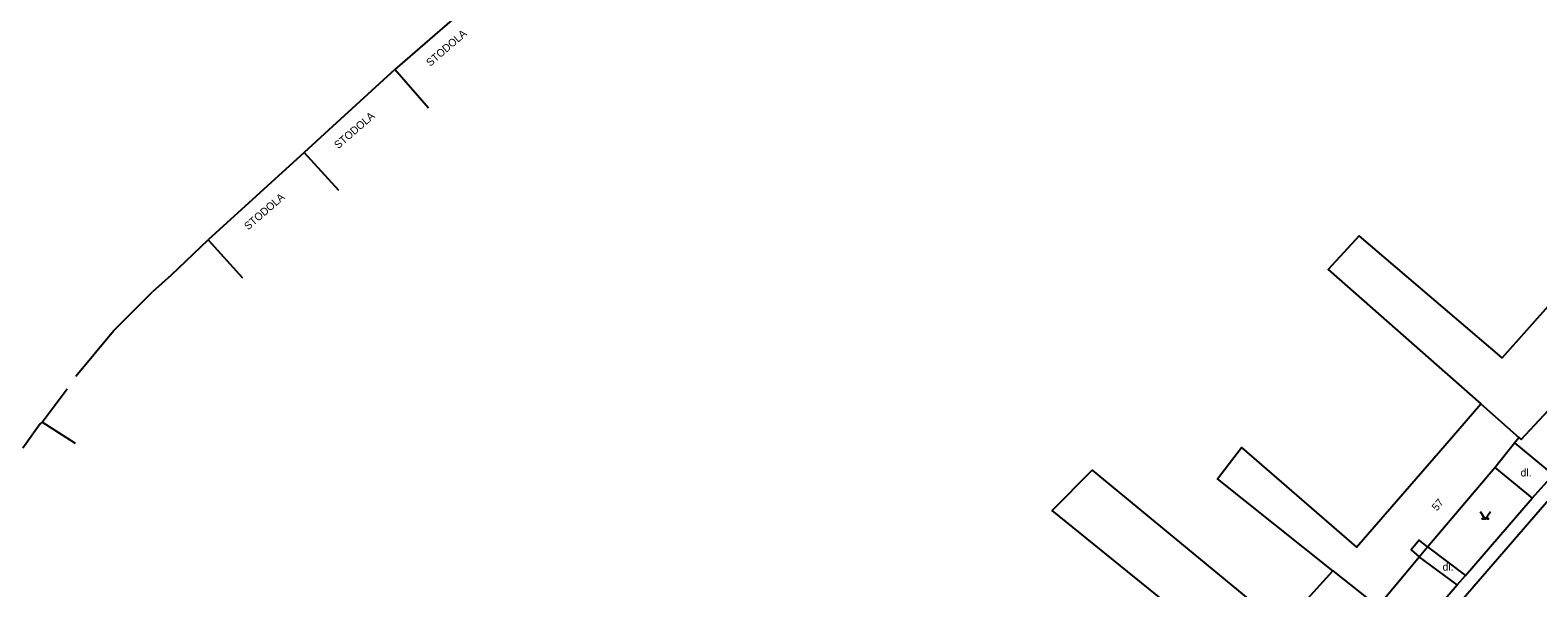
# Model space of a CAD drawing. Extents: x -582162 to -561283, y -1187583 to -1183539.
# Drawn here: x -570029.1 to -569882.3, y -1185267.1 to -1185212.7 of the extents above; entities that cross this region are included whole.
import ezdxf

# ---------------------------------------------------------------- set-up
doc = ezdxf.new("R2010")
doc.units = 0
for name, color, linetype in [('Vrstva 1', 7, 'Continuous'), ('Vrstva 10', 7, 'Continuous'), ('Vrstva 14', 7, 'Continuous'), ('Vrstva 3', 7, 'Continuous'), ('Vrstva 4', 7, 'Continuous'), ('Vrstva 5', 7, 'Continuous'), ('Vrstva 6', 7, 'Continuous'), ('Vrstva 9', 7, 'Continuous')]:
    doc.layers.add(name, color=color, linetype=linetype)

# ---------------------------------------------------------------- blocks, each defined once
blk = doc.blocks.new('3.140')
at = {"layer": 'Vrstva 1'}
blk.add_lwpolyline([(-1, 1.5), (0, 0), (1, 1.5)], dxfattribs=at)
for centre in [(-0.5, 0.1), (0.5, 0.1)]:
    blk.add_circle(centre, 0.1, dxfattribs=at)

msp = doc.modelspace()

# ---------------------------------------------------------------- linework, layer by layer
at = {"layer": 'Vrstva 10'}
for points in [[(-569914.2, -1185294.82), (-569909.01, -1185288.82), (-569896.95, -1185274.76), (-569894.46, -1185271.86), (-569890.1, -1185266.79), (-569889.3, -1185265.87), (-569882.8, -1185258.34), (-569880.78, -1185256.08), (-569875.08, -1185249.57)], [(-569884.54, -1185252.94), (-569880.78, -1185256.08)], [(-569917.9, -1185301.28), (-569889.1, -1185267.63), (-569878.07, -1185254.86)], [(-569886.46, -1185255.34), (-569882.8, -1185258.34)], [(-569893.01, -1185263.1), (-569889.3, -1185265.87)], [(-569890.1, -1185266.79), (-569893.81, -1185264.06)]]:
    msp.add_lwpolyline(points, dxfattribs=at)
at = {"layer": 'Vrstva 4'}
for points in [[(-569984.45, -1185208.87), (-569984.55, -1185208.76), (-569993.54, -1185216.57)], [(-569993.54, -1185216.57), (-570000, -1185222.47)], [(-569990.26, -1185220.35), (-569993.54, -1185216.57)], [(-570000, -1185222.47), (-570002.39, -1185224.65)], [(-570002.39, -1185224.65), (-570011.74, -1185233.16)], [(-570000, -1185227.27), (-570002.39, -1185224.65)], [(-569999.02, -1185228.35), (-570000, -1185227.27)], [(-570011.74, -1185233.16), (-570008.37, -1185236.86)], [(-569884.1, -1185252.42), (-569883.88, -1185252.62), (-569875.88, -1185244.05)], [(-569893.01, -1185263.1), (-569886.46, -1185255.34), (-569884.54, -1185252.94), (-569884.1, -1185252.42)], [(-569893.01, -1185263.1), (-569893.81, -1185262.44), (-569894.6, -1185263.39), (-569893.81, -1185264.06)], [(-569893.81, -1185264.06), (-569893.01, -1185263.1)], [(-569897.84, -1185268.9), (-569893.81, -1185264.06)]]:
    msp.add_lwpolyline(points, dxfattribs=at)
at = {"layer": 'Vrstva 5'}
for points in [[(-569881, -1185239.33), (-569885.72, -1185244.66), (-569899.66, -1185232.79), (-569902.66, -1185236.06), (-569887.81, -1185249.15), (-569884.1, -1185252.42)], [(-569902.23, -1185265.41), (-569913.45, -1185256.47), (-569911.1, -1185253.41), (-569899.92, -1185263.11), (-569890.67, -1185252.45), (-569887.81, -1185249.15)], [(-569910.78, -1185274.75), (-569929.54, -1185259.54), (-569925.64, -1185255.6), (-569907.15, -1185270.88), (-569902.23, -1185265.41), (-569897.84, -1185268.9)]]:
    msp.add_lwpolyline(points, dxfattribs=at)
at = {"layer": 'Vrstva 9'}
for points in [[(-570015.32, -1185236.6), (-570011.74, -1185233.16)], [(-570015.32, -1185236.6), (-570017.15, -1185238.23)], [(-570024.6, -1185246.44), (-570020.95, -1185242.03), (-570017.15, -1185238.23)], [(-570027.88, -1185250.94), (-570025.45, -1185247.7)], [(-570028.1, -1185251.11), (-570029.77, -1185253.47)], [(-570027.88, -1185250.94), (-570028.1, -1185251.11)], [(-570024.64, -1185253.01), (-570027.88, -1185250.94)]]:
    msp.add_lwpolyline(points, dxfattribs=at)

# ---------------------------------------------------------------- block references
at = {"layer": 'Vrstva 3', "xscale": 0.5, "yscale": 0.5}
msp.add_blockref('3.140', (-569887.37, -1185260.39), dxfattribs=at)

# ---------------------------------------------------------------- texts
at = {"layer": 'Vrstva 14'}
for p in [(-569990.1, -1185216.32), (-569999.06, -1185224.35), (-570007.83, -1185232.26)]:
    msp.add_text('STODOLA', height=0.75, rotation=40.982, dxfattribs=at).set_placement(p)
for p in [(-569883.93, -1185256.23), (-569891.53, -1185265.41)]:
    msp.add_text('dl.', height=0.75, dxfattribs=at).set_placement(p)
at = {"layer": 'Vrstva 6'}
msp.add_text('57', height=0.75, rotation=50.187, dxfattribs=at).set_placement((-569892.08, -1185259.65))

doc.saveas('drawing.dxf')
